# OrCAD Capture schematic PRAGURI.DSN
size A
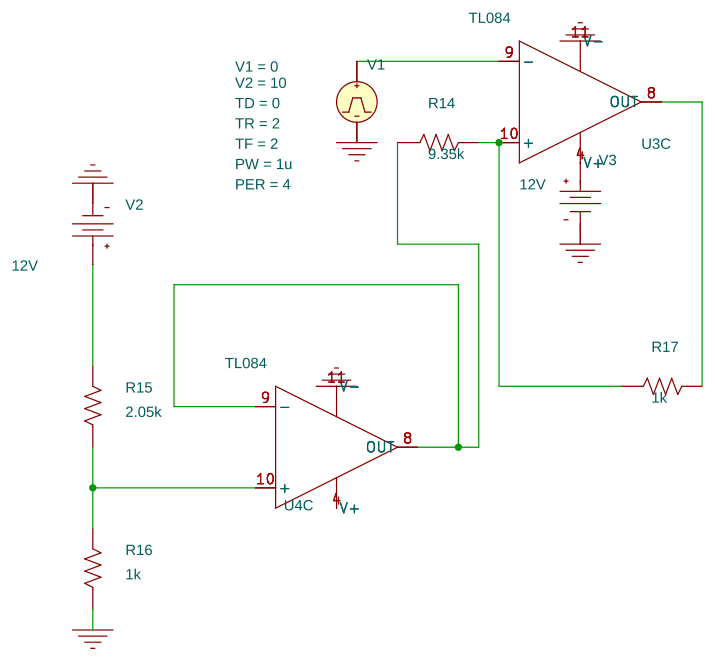
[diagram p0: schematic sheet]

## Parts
R14  9.35k  [AXRC05]
R15  2.05k  [AXRC05]
R16  1k  [AXRC05]
R17  1k  [AXRC05]
U3  TL084  [DIP10014W300L800]  (section C)
U4  TL084  [DIP10014W300L800]  (section C)
V1  VPULSE
V2  VDC
V3  VDC

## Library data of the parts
R14-R17 = R
U3 U4 = TL084
V1 = VPULSE: PER: 4; PW: 1u; TD: 0; TF: 2; TR: 2; V1: 0; V2: 10
V2 V3 = VDC: DC: 12V

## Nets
0: R16.1 U3.11(V-) U4.11(V-) V1.2(-) V2.1(-) V3.1(-)
V+: U4.4(V+)
N18720: U3.9(-) V1.1(+)
N18770: R17.2 U3.8(OUT)
N18808: R14.1 U4.8(OUT) U4.9(-)
N18812: R14.2 R17.1 U3.10(+)
N18886: R15.2 V2.0(+)
N18996: R15.1 R16.2 U4.10(+)
N19072: U3.4(V+) V3.0(+)
